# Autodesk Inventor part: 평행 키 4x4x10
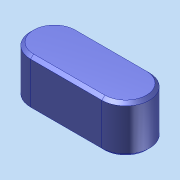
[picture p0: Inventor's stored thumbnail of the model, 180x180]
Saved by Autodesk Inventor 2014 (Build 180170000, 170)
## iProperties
Created: 2026-09
Part Number: 평행 키 4x4x10
Material: 일반
Document SubType Name: Modeling
Designer: dg
Density: 1 g/cm^3
Appearance: 기본값
Author: dg
Author: jhkim
Description: 키 및 해당 키홈
Creation Date: 2026-08-27
Sending System: Autodesk Inventor 2027
Preprocessor: ST-DEVELOPER v20.1
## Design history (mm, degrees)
node "평행 키 4x4x101"
body "Solid1"
node "기준1"
